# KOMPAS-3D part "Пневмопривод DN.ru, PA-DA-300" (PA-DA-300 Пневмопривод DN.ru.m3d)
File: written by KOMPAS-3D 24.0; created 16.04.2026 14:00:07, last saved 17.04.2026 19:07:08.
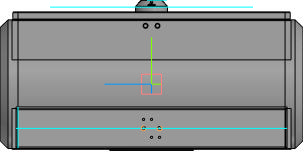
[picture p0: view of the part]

Document properties: Автор: DN.ru; Полное имя файла: C:\Работа\PA-DA-х Пневмопривод DN.ru\300\исходные материалы\PA-DA-300 Пневмопривод DN.ru.m3d

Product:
- Body: Тело 1  | qty 1
    Масса: 606.67872
- Body: Тело 2  | qty 1
    Масса: 606.67872
- Part/product: Пневмопривод DN.ru  | designation PA-DA-300
    Масса: 110
    Раздел спецификации: Прочие изделия
    Примечание: D290-00302

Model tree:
1. Эскиз:1
2. Элемент выдавливания:1
3. Эскиз:2  (with: Ребро.Элемент выдавливания:1)
4. Элемент выдавливания:2
5. Эскиз:3  (with: Ребро.Элемент выдавливания:2)
6. Элемент выдавливания:3  (with: Грань.Элемент выдавливания:2)
     Смещение 1 = -2; Расстояние 2 = 348; Смещение 2 = -2
7. Эскиз:4  (with: Грань.Элемент выдавливания:3)
8. Элемент выдавливания:4
9. Эскиз:6  (with: Ребро.Элемент выдавливания:2, Ребро.Элемент выдавливания:1)
10. Элемент выдавливания:6
11. Средняя плоскость:1  (with: Грань.Элемент выдавливания:6)
12. Отверстие:2  (with: Грань.Элемент выдавливания:6)
     Глубина выреза = 10; Диаметр отверстия = 6; Угол конуса дна = 120; Расстояние 2 = -22.5
13. Массив по сетке:2  (with: Отверстие:2)  (3 pattern instances)
     Шаг 1 = 20; Угол раствора = 90; Шаг 2 = 45
14. Массив по сетке:3  (with: Отверстие:2)  (2 pattern instances)
     Шаг 1 = 45; Угол раствора = 90; Шаг 2 = 20
15. Отверстие:3  (with: Грань.Элемент выдавливания:6)  (labels: W 1/2'')
     Глубина выреза = 10; Диаметр отверстия = 9.98886; Угол конуса дна = 120; Расстояние 1 = 20
16. W 1/2''  (with: Грань.Отверстие:3, Грань.Элемент выдавливания:6)  (labels: cil5_ex_DIN 477 BSW coarse)
     Длина резьбы = 8; Шаг резьбы = 2.117; Номинальный диаметр резьбы = 12.7
17. Массив по сетке:4  (with: Отверстие:3)  (labels: W 1/2'')  (2 pattern instances)
18. W 1/4''  (with: Грань.Отверстие:3, Грань.Элемент выдавливания:6)  (labels: cil5_ex_DIN 477 BSW coarse)
     Длина резьбы = 8; Шаг резьбы = 2.117; Номинальный диаметр резьбы = 12.7; Шаг 1 = 40; Угол раствора = 90; Шаг 2 = 10
19. Эскиз:7  (with: Грань.Элемент выдавливания:2)
20. Элемент выдавливания:7
21. Эскиз:8  (with: Грань.Элемент выдавливания:2, Ребро.Элемент выдавливания:2)
22. Элемент выдавливания:8  (with: Грань.Элемент выдавливания:6)
     Расстояние 2 = 4
23. Отверстие:4  (with: Грань.Элемент выдавливания:2)
     Глубина выреза = 7; Диаметр отверстия = 10; Угол конуса дна = 118; Расстояние 1 = 15; Расстояние 2 = 15; Диаметр зенковки = 13.2; Глубина зенковки = 1.6; Угол зенковки = 90
24. Массив по сетке:5  (with: Отверстие:4)  (2 pattern instances)
     Шаг 1 = 30; Угол раствора = 90
25. Отверстие:5  (with: Грань.Элемент выдавливания:3)
     Глубина выреза = 10; Диаметр отверстия = 5; Угол конуса дна = 120; Диаметр зенковки = 7; Глубина зенковки = 1; Угол зенковки = 90
26. Массив по сетке:6  (with: Отверстие:5)  (4 pattern instances)
     Угол раствора = 90
27. Фаска:1  (with: Ребро.Элемент выдавливания:4)
     Угол = 45; Длина 1 = 15; Длина 2 = 15
28. Скругление:2  (with: Ребро.Элемент выдавливания:3)
     Радиус = 2
29. Скругление:3  (with: Ребро.Элемент выдавливания:6)
     Радиус = 3
30. Скругление:4  (with: Ребро.Элемент выдавливания:8, Ребро.Элемент выдавливания:2)
     Радиус = 2
31. Скругление:5  (with: Ребро.Элемент выдавливания:6)
     Радиус = 3
32. Смещенная плоскость:1  (with: Грань.Элемент выдавливания:3)
33. Эскиз:9
34. Элемент выдавливания:9  (with: Грань.Фаска:1)
     Расстояние 1 = 43.4142; Смещение 1 = 1
35. Смещенная плоскость:2  (with: Грань.Элемент выдавливания:4)
     Расстояние = 0.5
36. Эскиз:10
37. Элемент выдавливания:10
     Расстояние 1 = 25.9142
38. Эскиз:11  (with: Грань.Элемент выдавливания:4)
39. Элемент выдавливания:11
     Расстояние 1 = 1
40. Эскиз:12  (with: Грань.Элемент выдавливания:11, Ребро.Элемент выдавливания:11)
41. Элемент выдавливания:12  (with: Грань.Элемент выдавливания:4)
     Расстояние 2 = 1
42. Эскиз:13  (with: Грань.Элемент выдавливания:11)
43. Элемент выдавливания:13  (with: Грань.Элемент выдавливания:4)
     Расстояние 2 = 1
44. Скругление:7  (with: Ребро.Элемент выдавливания:11)
     Радиус = 1
45. Скругление:8  (with: Ребро.Элемент выдавливания:8)
     Радиус = 2
46. Эскиз:14  (with: Грань.Элемент выдавливания:3)
47. Элемент выдавливания:14  (with: Грань.Фаска:1)
     Расстояние 1 = 54.1414; Смещение 1 = 0.1
48. Эскиз:15  (with: Грань.Элемент выдавливания:3, Ребро.Скругление:2)
49. Элемент выдавливания:15
     Расстояние 2 = 0.1
50. Отверстие:6  (with: Грань.Элемент выдавливания:2, Ребро.Элемент выдавливания:2)
     Глубина выреза = 10; Диаметр отверстия = 20; Угол конуса дна = 118; Расстояние 1 = 25; Расстояние 2 = 25; Диаметр цековки = 35; Глубина цековки = 5
51. Зеркальный массив:1
52. Экземпляр ( 1 )
53. Экземпляр ( 2 )  (with: Отверстие:6)
54. Зеркальный массив:2  (with: Экземпляр ( 1 ), Экземпляр ( 2 ), Отверстие:6)
55. Зеркальный массив:3  (with: Экземпляр ( 1 ), Экземпляр ( 2 ), Зеркальный массив:2, Отверстие:6)
56. Зеркальный массив:4  (with: Экземпляр ( 1 ), Экземпляр ( 2 ), Зеркальный массив:1, Отверстие:6, Зеркальный массив:3, Зеркальный массив:2)
57. Фаска:2  (with: Ребро.Элемент выдавливания:7)
     Угол = 45; Длина 1 = 2.5; Длина 2 = 2.5
58. Фаска:3  (with: Ребро.Элемент выдавливания:1)
     Угол = 45; Длина 1 = 20; Длина 2 = 20
59. Смещенная плоскость:3  (with: Грань.Элемент выдавливания:6)
     Расстояние = 5
60. Эскиз:16
61. Элемент выдавливания:16
     Расстояние 2 = 0.1
62. Зеркальный массив:5  (with: Экземпляр ( 1 ), Экземпляр ( 2 ), Элемент выдавливания:16)

Expressions: H/2; -G/2; v2053*2; (E-D-6)/2
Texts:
  PA-DA-300
  GOST 26.020 Pr3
